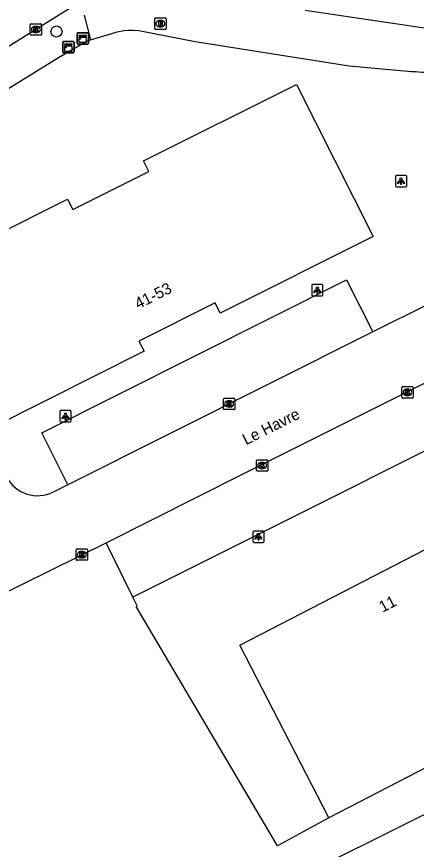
# Model space of a CAD drawing. Extents: x 158461 to 159795, y 387220 to 388672.
# Drawn here: x 158950.9 to 158986.1, y 387648.6 to 387722 of the extents above; entities that cross this region are included whole.
import ezdxf

# ---------------------------------------------------------------- set-up
doc = ezdxf.new("R2010")
doc.units = 0
for name, color, linetype in [('IMGEO_Boom', 7, 'Continuous'), ('IMGEO_Brandkraan', 7, 'Continuous'), ('IMGEO_Groenvoorziening', 7, 'Continuous'), ('IMGEO_Kast', 7, 'Continuous'), ('IMGEO_Kolk', 7, 'Continuous'), ('IMGEO_Lichtpunt', 7, 'Continuous'), ('IMGEO_Openbare_ruimte_label', 7, 'Continuous'), ('IMGEO_Pand', 7, 'Continuous'), ('IMGEO_Pand_nummerreeks', 7, 'Continuous'), ('IMGEO_Parkeervlak_open', 7, 'Continuous'), ('IMGEO_Rijbaan_lokaal_gesloten', 7, 'Continuous'), ('IMGEO_Rijbaan_lokaal_open', 7, 'Continuous'), ('IMGEO_Voetpad_open', 7, 'Continuous')]:
    doc.layers.add(name, color=color, linetype=linetype)

msp = doc.modelspace()

# ---------------------------------------------------------------- linework, layer by layer
at = {"layer": 'IMGEO_Boom'}
msp.add_circle((158954.397, 387720.713), 0.489, dxfattribs=at)
at = {"layer": 'IMGEO_Brandkraan'}
for p, q in [((158963.041, 387720.979), (158963.041, 387721.831)), ((158963.116, 387721.905), (158963.968, 387721.905)), ((158963.529, 387721.685), (158963.554, 387721.685)), ((158964.042, 387721.831), (158964.042, 387720.979)), ((158963.968, 387720.905), (158963.116, 387720.905)), ((158963.552, 387721.125), (158963.527, 387721.125))]:
    msp.add_line(p, q, dxfattribs=at)
for points in [[(158963.041, 387720.979), (158963.041, 387721.831)], [(158963.116, 387721.905), (158963.968, 387721.905)], [(158963.389, 387721.605), (158963.389, 387721.205), (158963.602, 387721.205)], [(158963.62, 387721.605), (158963.389, 387721.605)], [(158963.568, 387721.524), (158963.514, 387721.524), (158963.514, 387721.448)], [(158964.042, 387721.831), (158964.042, 387720.979)], [(158963.968, 387720.905), (158963.116, 387720.905)], [(158963.514, 387721.448), (158963.567, 387721.448)], [(158963.576, 387721.372), (158963.514, 387721.372), (158963.514, 387721.291)], [(158963.514, 387721.291), (158963.576, 387721.291)]]:
    msp.add_lwpolyline(points, dxfattribs=at)
for centre, radius, start, end in [((158963.118, 387721.829), 0.0765, 91.55205, 178.44795), ((158963.118, 387721.829), 0.0765, 91.55205, 178.44795), ((158963.569, 387721.486), 0.0379, 267.82845, 90.93552), ((158963.624, 387721.46), 0.145, 59.4692, 91.53667), ((158963.649, 387721.507), 0.0922, 285.51372, 58.15012), ((158963.966, 387721.829), 0.0765, 1.55205, 88.44795), ((158963.966, 387721.829), 0.0765, 1.55205, 88.44795), ((158963.118, 387720.981), 0.0765, 181.55205, 268.44795), ((158963.118, 387720.981), 0.0765, 181.55205, 268.44795), ((158963.577, 387721.331), 0.0404, 269.87594, 90.50774), ((158963.608, 387721.456), 0.251, 268.66757, 293.53466), ((158963.654, 387721.315), 0.105, 301.31148, 78.98903), ((158963.966, 387720.981), 0.0765, 271.55205, 358.44795), ((158963.966, 387720.981), 0.0765, 271.55205, 358.44795)]:
    msp.add_arc(centre, radius, start, end, dxfattribs=at)
for centre, major_axis, ratio, start_param, end_param in [((158963.528, 387721.405), (-0.387, 0.002), 0.722429, 4.712389, 7.853982), ((158963.553, 387721.405), (-0.39, 0.002), 0.717154, 1.570796, 4.712389)]:
    msp.add_ellipse(centre, major_axis=major_axis, ratio=ratio, start_param=start_param, end_param=end_param, dxfattribs=at)
at = {"layer": 'IMGEO_Groenvoorziening'}
msp.add_lwpolyline([(158978.384, 387651.425), (158973.845, 387648.946), (158961.411, 387670.041), (158961.498, 387670.092), (158961.124, 387670.85)], dxfattribs=at)
at = {"layer": 'IMGEO_Kast'}
for p, q in [((158956.204, 387719.68), (158956.204, 387720.521)), ((158956.204, 387720.521), (158956.204, 387719.68)), ((158956.279, 387720.605), (158957.12, 387720.605)), ((158957.12, 387720.605), (158956.279, 387720.605)), ((158957.204, 387720.53), (158957.204, 387719.689)), ((158957.204, 387719.689), (158957.204, 387720.53)), ((158954.938, 387718.911), (158954.938, 387719.752)), ((158954.938, 387719.752), (158954.938, 387718.911)), ((158955.013, 387719.836), (158955.854, 387719.836)), ((158955.854, 387719.836), (158955.013, 387719.836)), ((158955.938, 387719.761), (158955.938, 387718.92)), ((158955.938, 387718.92), (158955.938, 387719.761)), ((158957.129, 387719.605), (158956.288, 387719.605)), ((158956.288, 387719.605), (158957.129, 387719.605)), ((158955.863, 387718.836), (158955.022, 387718.836)), ((158955.022, 387718.836), (158955.863, 387718.836))]:
    msp.add_line(p, q, dxfattribs=at)
for points in [[(158956.399, 387720.395), (158956.999, 387720.395), (158956.999, 387720.31), (158956.399, 387720.31), (158956.399, 387720.395)], [(158956.399, 387720.22), (158956.999, 387720.22), (158956.999, 387719.731), (158956.399, 387719.731), (158956.399, 387720.22)], [(158955.133, 387719.626), (158955.733, 387719.626), (158955.733, 387719.541), (158955.133, 387719.541), (158955.133, 387719.626)], [(158955.133, 387719.451), (158955.733, 387719.451), (158955.733, 387718.962), (158955.133, 387718.962), (158955.133, 387719.451)]]:
    msp.add_lwpolyline(points, dxfattribs=at)
for centre in [(158956.483, 387720.069), (158955.217, 387719.3)]:
    msp.add_circle(centre, 0.0377, dxfattribs=at)
for centre, start, end in [((158956.282, 387720.527), 92.4484, 184.28452), ((158956.282, 387720.527), 92.4484, 184.28452), ((158957.126, 387720.527), 2.4484, 94.28452), ((158957.126, 387720.527), 2.4484, 94.28452), ((158955.016, 387719.758), 92.4484, 184.28452), ((158955.016, 387719.758), 92.4484, 184.28452), ((158955.86, 387719.758), 2.4484, 94.28452), ((158955.86, 387719.758), 2.4484, 94.28452), ((158956.282, 387719.683), 182.4484, 274.28452), ((158956.282, 387719.683), 182.4484, 274.28452), ((158957.126, 387719.683), 272.4484, 4.28452), ((158957.126, 387719.683), 272.4484, 4.28452), ((158955.016, 387718.914), 182.4484, 274.28452), ((158955.016, 387718.914), 182.4484, 274.28452), ((158955.86, 387718.914), 272.4484, 4.28452), ((158955.86, 387718.914), 272.4484, 4.28452)]:
    msp.add_arc(centre, 0.0779, start, end, dxfattribs=at)
at = {"layer": 'IMGEO_Kolk'}
for p, q in [((158952.08, 387720.459), (158952.08, 387721.311)), ((158952.155, 387721.385), (158953.007, 387721.385)), ((158952.568, 387721.165), (158952.593, 387721.165)), ((158953.081, 387721.311), (158953.081, 387720.459)), ((158953.007, 387720.385), (158952.155, 387720.385)), ((158952.591, 387720.605), (158952.566, 387720.605)), ((158984.807, 387688.49), (158984.807, 387689.342)), ((158984.882, 387689.416), (158985.734, 387689.416)), ((158985.808, 387689.342), (158985.808, 387688.49)), ((158985.318, 387688.636), (158985.293, 387688.636)), ((158985.295, 387689.196), (158985.32, 387689.196)), ((158969.092, 387687.468), (158969.092, 387688.32)), ((158969.167, 387688.394), (158970.019, 387688.394)), ((158969.58, 387688.174), (158969.605, 387688.174)), ((158970.093, 387688.32), (158970.093, 387687.468)), ((158985.734, 387688.416), (158984.882, 387688.416)), ((158970.019, 387687.394), (158969.167, 387687.394)), ((158969.603, 387687.614), (158969.578, 387687.614)), ((158971.998, 387682.039), (158971.998, 387682.891)), ((158972.073, 387682.965), (158972.925, 387682.965)), ((158972.486, 387682.745), (158972.511, 387682.745)), ((158972.999, 387682.891), (158972.999, 387682.039)), ((158972.925, 387681.965), (158972.073, 387681.965)), ((158972.509, 387682.185), (158972.484, 387682.185)), ((158956.126, 387674.185), (158956.126, 387675.037)), ((158956.201, 387675.111), (158957.053, 387675.111)), ((158956.614, 387674.891), (158956.639, 387674.891)), ((158957.127, 387675.037), (158957.127, 387674.185)), ((158957.053, 387674.111), (158956.201, 387674.111)), ((158956.637, 387674.331), (158956.612, 387674.331))]:
    msp.add_line(p, q, dxfattribs=at)
for points in [[(158952.08, 387720.459), (158952.08, 387721.311)], [(158952.155, 387721.385), (158953.007, 387721.385)], [(158952.401, 387721.085), (158952.524, 387721.085), (158952.524, 387720.934), (158952.654, 387721.085), (158952.818, 387721.085), (158952.672, 387720.934), (158952.825, 387720.685), (158952.673, 387720.685), (158952.588, 387720.849), (158952.524, 387720.782), (158952.524, 387720.685), (158952.401, 387720.685), (158952.401, 387721.085)], [(158953.081, 387721.311), (158953.081, 387720.459)], [(158953.007, 387720.385), (158952.155, 387720.385)], [(158984.807, 387688.49), (158984.807, 387689.342)], [(158984.882, 387689.416), (158985.734, 387689.416)], [(158985.808, 387689.342), (158985.808, 387688.49)], [(158985.128, 387689.116), (158985.251, 387689.116), (158985.251, 387688.965), (158985.381, 387689.116), (158985.545, 387689.116), (158985.399, 387688.965), (158985.552, 387688.716), (158985.4, 387688.716), (158985.315, 387688.88), (158985.251, 387688.813), (158985.251, 387688.716), (158985.128, 387688.716), (158985.128, 387689.116)], [(158969.092, 387687.468), (158969.092, 387688.32)], [(158969.167, 387688.394), (158970.019, 387688.394)], [(158969.413, 387688.094), (158969.536, 387688.094), (158969.536, 387687.943), (158969.666, 387688.094), (158969.83, 387688.094), (158969.684, 387687.943), (158969.837, 387687.694), (158969.685, 387687.694), (158969.6, 387687.858), (158969.536, 387687.791), (158969.536, 387687.694), (158969.413, 387687.694), (158969.413, 387688.094)], [(158970.093, 387688.32), (158970.093, 387687.468)], [(158985.734, 387688.416), (158984.882, 387688.416)], [(158970.019, 387687.394), (158969.167, 387687.394)], [(158971.998, 387682.039), (158971.998, 387682.891)], [(158972.073, 387682.965), (158972.925, 387682.965)], [(158972.319, 387682.665), (158972.442, 387682.665), (158972.442, 387682.514), (158972.572, 387682.665), (158972.736, 387682.665), (158972.59, 387682.514), (158972.743, 387682.265), (158972.591, 387682.265), (158972.506, 387682.429), (158972.442, 387682.362), (158972.442, 387682.265), (158972.319, 387682.265), (158972.319, 387682.665)], [(158972.999, 387682.891), (158972.999, 387682.039)], [(158972.925, 387681.965), (158972.073, 387681.965)], [(158956.126, 387674.185), (158956.126, 387675.037)], [(158956.201, 387675.111), (158957.053, 387675.111)], [(158956.447, 387674.811), (158956.57, 387674.811), (158956.57, 387674.66), (158956.7, 387674.811), (158956.864, 387674.811), (158956.718, 387674.66), (158956.871, 387674.411), (158956.719, 387674.411), (158956.634, 387674.575), (158956.57, 387674.508), (158956.57, 387674.411), (158956.447, 387674.411), (158956.447, 387674.811)], [(158957.127, 387675.037), (158957.127, 387674.185)], [(158957.053, 387674.111), (158956.201, 387674.111)]]:
    msp.add_lwpolyline(points, dxfattribs=at)
for centre, start, end in [((158952.157, 387721.309), 91.55205, 178.44795), ((158952.157, 387721.309), 91.55205, 178.44795), ((158953.005, 387721.309), 1.55205, 88.44795), ((158953.005, 387721.309), 1.55205, 88.44795), ((158952.157, 387720.461), 181.55205, 268.44795), ((158952.157, 387720.461), 181.55205, 268.44795), ((158953.005, 387720.461), 271.55205, 358.44795), ((158953.005, 387720.461), 271.55205, 358.44795), ((158984.884, 387689.34), 91.55205, 178.44795), ((158984.884, 387689.34), 91.55205, 178.44795), ((158985.732, 387689.34), 1.55205, 88.44795), ((158985.732, 387689.34), 1.55205, 88.44795), ((158969.169, 387688.318), 91.55205, 178.44795), ((158969.169, 387688.318), 91.55205, 178.44795), ((158970.017, 387688.318), 1.55205, 88.44795), ((158970.017, 387688.318), 1.55205, 88.44795), ((158984.884, 387688.492), 181.55205, 268.44795), ((158984.884, 387688.492), 181.55205, 268.44795), ((158985.732, 387688.492), 271.55205, 358.44795), ((158985.732, 387688.492), 271.55205, 358.44795), ((158969.169, 387687.47), 181.55205, 268.44795), ((158969.169, 387687.47), 181.55205, 268.44795), ((158970.017, 387687.47), 271.55205, 358.44795), ((158970.017, 387687.47), 271.55205, 358.44795), ((158972.075, 387682.889), 91.55205, 178.44795), ((158972.075, 387682.889), 91.55205, 178.44795), ((158972.923, 387682.889), 1.55205, 88.44795), ((158972.923, 387682.889), 1.55205, 88.44795), ((158972.075, 387682.041), 181.55205, 268.44795), ((158972.075, 387682.041), 181.55205, 268.44795), ((158972.923, 387682.041), 271.55205, 358.44795), ((158972.923, 387682.041), 271.55205, 358.44795), ((158956.203, 387675.035), 91.55205, 178.44795), ((158956.203, 387675.035), 91.55205, 178.44795), ((158957.051, 387675.035), 1.55205, 88.44795), ((158957.051, 387675.035), 1.55205, 88.44795), ((158956.203, 387674.187), 181.55205, 268.44795), ((158956.203, 387674.187), 181.55205, 268.44795), ((158957.051, 387674.187), 271.55205, 358.44795), ((158957.051, 387674.187), 271.55205, 358.44795)]:
    msp.add_arc(centre, 0.0765, start, end, dxfattribs=at)
for centre, major_axis, ratio, start_param, end_param in [((158952.567, 387720.885), (-0.387, 0.002), 0.722429, 4.712389, 7.853982), ((158952.592, 387720.885), (-0.39, 0.002), 0.717154, 1.570796, 4.712389), ((158985.294, 387688.916), (-0.387, 0.002), 0.722429, 4.712389, 7.853982), ((158985.319, 387688.916), (-0.39, 0.002), 0.717154, 1.570796, 4.712389), ((158969.579, 387687.894), (-0.387, 0.002), 0.722429, 4.712389, 7.853982), ((158969.604, 387687.894), (-0.39, 0.002), 0.717154, 1.570796, 4.712389), ((158972.485, 387682.465), (-0.387, 0.002), 0.722429, 4.712389, 7.853982), ((158972.51, 387682.465), (-0.39, 0.002), 0.717154, 1.570796, 4.712389), ((158956.613, 387674.611), (-0.387, 0.002), 0.722429, 4.712389, 7.853982), ((158956.638, 387674.611), (-0.39, 0.002), 0.717154, 1.570796, 4.712389)]:
    msp.add_ellipse(centre, major_axis=major_axis, ratio=ratio, start_param=start_param, end_param=end_param, dxfattribs=at)
at = {"layer": 'IMGEO_Lichtpunt'}
for p, q in [((158984.236, 387707.928), (158984.236, 387707.121)), ((158984.236, 387707.928), (158984.236, 387707.121)), ((158985.138, 387708.023), (158984.33, 387708.023)), ((158985.138, 387708.023), (158984.33, 387708.023)), ((158985.232, 387707.121), (158985.232, 387707.928)), ((158985.232, 387707.121), (158985.232, 387707.928)), ((158984.33, 387707.027), (158985.138, 387707.027)), ((158984.33, 387707.027), (158985.138, 387707.027)), ((158976.864, 387698.322), (158976.864, 387697.515)), ((158976.864, 387698.322), (158976.864, 387697.515)), ((158977.766, 387698.417), (158976.958, 387698.417)), ((158977.766, 387698.417), (158976.958, 387698.417)), ((158977.86, 387697.515), (158977.86, 387698.322)), ((158977.86, 387697.515), (158977.86, 387698.322)), ((158976.958, 387697.421), (158977.766, 387697.421)), ((158976.958, 387697.421), (158977.766, 387697.421)), ((158954.686, 387687.207), (158954.686, 387686.4)), ((158954.686, 387687.207), (158954.686, 387686.4)), ((158955.588, 387687.302), (158954.78, 387687.302)), ((158955.588, 387687.302), (158954.78, 387687.302)), ((158955.682, 387686.4), (158955.682, 387687.207)), ((158955.682, 387686.4), (158955.682, 387687.207)), ((158954.78, 387686.306), (158955.588, 387686.306)), ((158954.78, 387686.306), (158955.588, 387686.306)), ((158971.677, 387676.597), (158971.677, 387675.79)), ((158971.677, 387676.597), (158971.677, 387675.79)), ((158972.579, 387676.692), (158971.771, 387676.692)), ((158972.579, 387676.692), (158971.771, 387676.692)), ((158972.673, 387675.79), (158972.673, 387676.597)), ((158972.673, 387675.79), (158972.673, 387676.597)), ((158971.771, 387675.696), (158972.579, 387675.696)), ((158971.771, 387675.696), (158972.579, 387675.696))]:
    msp.add_line(p, q, dxfattribs=at)
for points in [[(158984.61, 387707.592), (158984.649, 387707.564), (158984.461, 387707.302), (158984.423, 387707.329), (158984.61, 387707.592)], [(158984.822, 387707.564), (158984.86, 387707.591), (158985.047, 387707.329), (158985.008, 387707.301), (158984.822, 387707.564)], [(158984.712, 387707.544), (158984.759, 387707.544), (158984.759, 387707.222), (158984.712, 387707.222), (158984.712, 387707.544)], [(158977.238, 387697.986), (158977.277, 387697.958), (158977.089, 387697.696), (158977.051, 387697.723), (158977.238, 387697.986)], [(158977.34, 387697.938), (158977.387, 387697.938), (158977.387, 387697.616), (158977.34, 387697.616), (158977.34, 387697.938)], [(158977.45, 387697.958), (158977.488, 387697.985), (158977.675, 387697.723), (158977.636, 387697.695), (158977.45, 387697.958)], [(158955.06, 387686.871), (158955.099, 387686.843), (158954.911, 387686.581), (158954.873, 387686.608), (158955.06, 387686.871)], [(158955.162, 387686.823), (158955.209, 387686.823), (158955.209, 387686.501), (158955.162, 387686.501), (158955.162, 387686.823)], [(158955.272, 387686.843), (158955.31, 387686.87), (158955.497, 387686.608), (158955.458, 387686.58), (158955.272, 387686.843)], [(158972.051, 387676.261), (158972.09, 387676.233), (158971.902, 387675.971), (158971.864, 387675.998), (158972.051, 387676.261)], [(158972.153, 387676.213), (158972.2, 387676.213), (158972.2, 387675.891), (158972.153, 387675.891), (158972.153, 387676.213)], [(158972.263, 387676.233), (158972.301, 387676.26), (158972.488, 387675.998), (158972.449, 387675.97), (158972.263, 387676.233)]]:
    msp.add_lwpolyline(points, dxfattribs=at)
for centre in [(158984.735, 387707.726), (158977.363, 387698.12), (158955.185, 387687.005), (158972.176, 387676.395)]:
    msp.add_circle(centre, 0.0994, dxfattribs=at)
for centre, start, end in [((158984.33, 387707.928), 90, 180), ((158984.33, 387707.928), 90, 180), ((158985.138, 387707.928), 0, 90), ((158985.138, 387707.928), 0, 90), ((158984.33, 387707.121), 180, 270), ((158984.33, 387707.121), 180, 270), ((158985.138, 387707.121), 270, 0), ((158985.138, 387707.121), 270, 360), ((158976.958, 387698.322), 90, 180), ((158976.958, 387698.322), 90, 180), ((158977.766, 387698.322), 0, 90), ((158977.766, 387698.322), 0, 90), ((158976.958, 387697.515), 180, 270), ((158976.958, 387697.515), 180, 270), ((158977.766, 387697.515), 270, 0), ((158977.766, 387697.515), 270, 360), ((158954.78, 387687.207), 90, 180), ((158954.78, 387687.207), 90, 180), ((158955.588, 387687.207), 0, 90), ((158955.588, 387687.207), 0, 90), ((158954.78, 387686.4), 180, 270), ((158954.78, 387686.4), 180, 270), ((158955.588, 387686.4), 270, 0), ((158955.588, 387686.4), 270, 360), ((158971.771, 387676.597), 90, 180), ((158971.771, 387676.597), 90, 180), ((158972.579, 387676.597), 0, 90), ((158972.579, 387676.597), 0, 90), ((158971.771, 387675.79), 180, 270), ((158971.771, 387675.79), 180, 270), ((158972.579, 387675.79), 270, 0), ((158972.579, 387675.79), 270, 360)]:
    msp.add_arc(centre, 0.0946, start, end, dxfattribs=at)
at = {"layer": 'IMGEO_Pand'}
for points in [[(158955.367, 387705.953), (158955.839, 387705.015), (158962.538, 387708.373), (158962.052, 387709.312), (158975.532, 387716.033), (158982.269, 387702.649), (158968.817, 387695.897), (158968.368, 387696.806), (158961.652, 387693.436), (158962.105, 387692.533), (158948.665, 387685.783), (158941.942, 387699.204), (158955.367, 387705.953)], [(158978.384, 387651.425), (158970.526, 387666.636), (158994.143, 387678.837)], [(159000.123, 387662.655), (158978.384, 387651.425)]]:
    msp.add_lwpolyline(points, dxfattribs=at)
at = {"layer": 'IMGEO_Parkeervlak_open'}
for points in [[(158955.393, 387680.776), (158953.099, 387685.358), (158979.936, 387698.826), (158982.246, 387694.247)], [(158990.433, 387685.56), (158973.044, 387676.827), (158961.124, 387670.85)], [(158961.124, 387670.85), (158958.754, 387675.659)], [(158946.279, 387626.609), (158944.377, 387630.625), (159006.332, 387661.445), (159008.345, 387657.448)]]:
    msp.add_lwpolyline(points, dxfattribs=at)
at = {"layer": 'IMGEO_Rijbaan_lokaal_gesloten'}
for points in [[(159022.447, 387725.145), (159009.709, 387721.727), (158989.772, 387720.574), (158976.287, 387722.576)], [(158956.215, 387723.154), (158935.881, 387710.493)]]:
    msp.add_lwpolyline(points, dxfattribs=at)
at = {"layer": 'IMGEO_Rijbaan_lokaal_open'}
for points in [[(158932.006, 387704.453), (158948.984, 387670.834), (158958.754, 387675.659)], [(158992.385, 387700.116), (158992.424, 387699.679), (158991.942, 387699.057), (158982.246, 387694.247)], [(158982.246, 387694.247), (158955.393, 387680.776)], [(158958.754, 387675.659), (158970.817, 387681.727), (158988.077, 387690.38)], [(158955.393, 387680.776), (158954.104, 387680.116)]]:
    msp.add_lwpolyline(points, dxfattribs=at)
msp.add_arc((158952.746, 387682.92), 3.115, 208.37861, 295.84521, dxfattribs=at)
at = {"layer": 'IMGEO_Voetpad_open'}
for points in [[(158956.816, 387722.141), (158957.387, 387719.979)], [(158957.387, 387719.979), (158959.267, 387720.535), (158959.734, 387720.672), (158960.355, 387720.802), (158960.683, 387720.83), (158961.168, 387720.829), (158961.655, 387720.802), (158966.605, 387719.828), (158980.163, 387717.679), (158985.663, 387717.203)], [(158957.387, 387719.979), (158956.956, 387719.769), (158954.576, 387718.383), (158941.994, 387710.653), (158937.469, 387707.844)]]:
    msp.add_lwpolyline(points, dxfattribs=at)
msp.add_arc((158987.649, 387738.893), 21.78, 264.76736, 278.29335, dxfattribs=at)

# ---------------------------------------------------------------- texts
at = {"layer": 'IMGEO_Openbare_ruimte_label'}
msp.add_text('Le Havre', height=1, rotation=26.6163, dxfattribs=at).set_placement((158971.084, 387684.241))
at = {"layer": 'IMGEO_Pand_nummerreeks'}
for s, rotation, p in [('41-53', 26.64689, (158961.589, 387696.224)), ('11', 27.14728, (158983.11, 387669.49))]:
    msp.add_text(s, height=1, rotation=rotation, dxfattribs=at).set_placement(p)

doc.saveas('drawing.dxf')
